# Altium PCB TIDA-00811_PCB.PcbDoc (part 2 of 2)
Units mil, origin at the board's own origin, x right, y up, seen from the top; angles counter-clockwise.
Board outline 3346.46 x 1968.5 mil, 2 copper layers (Top Layer, Bottom Layer), stack 62 mil thick; 221 components, 100 nets, 529 pads, 192 vias.
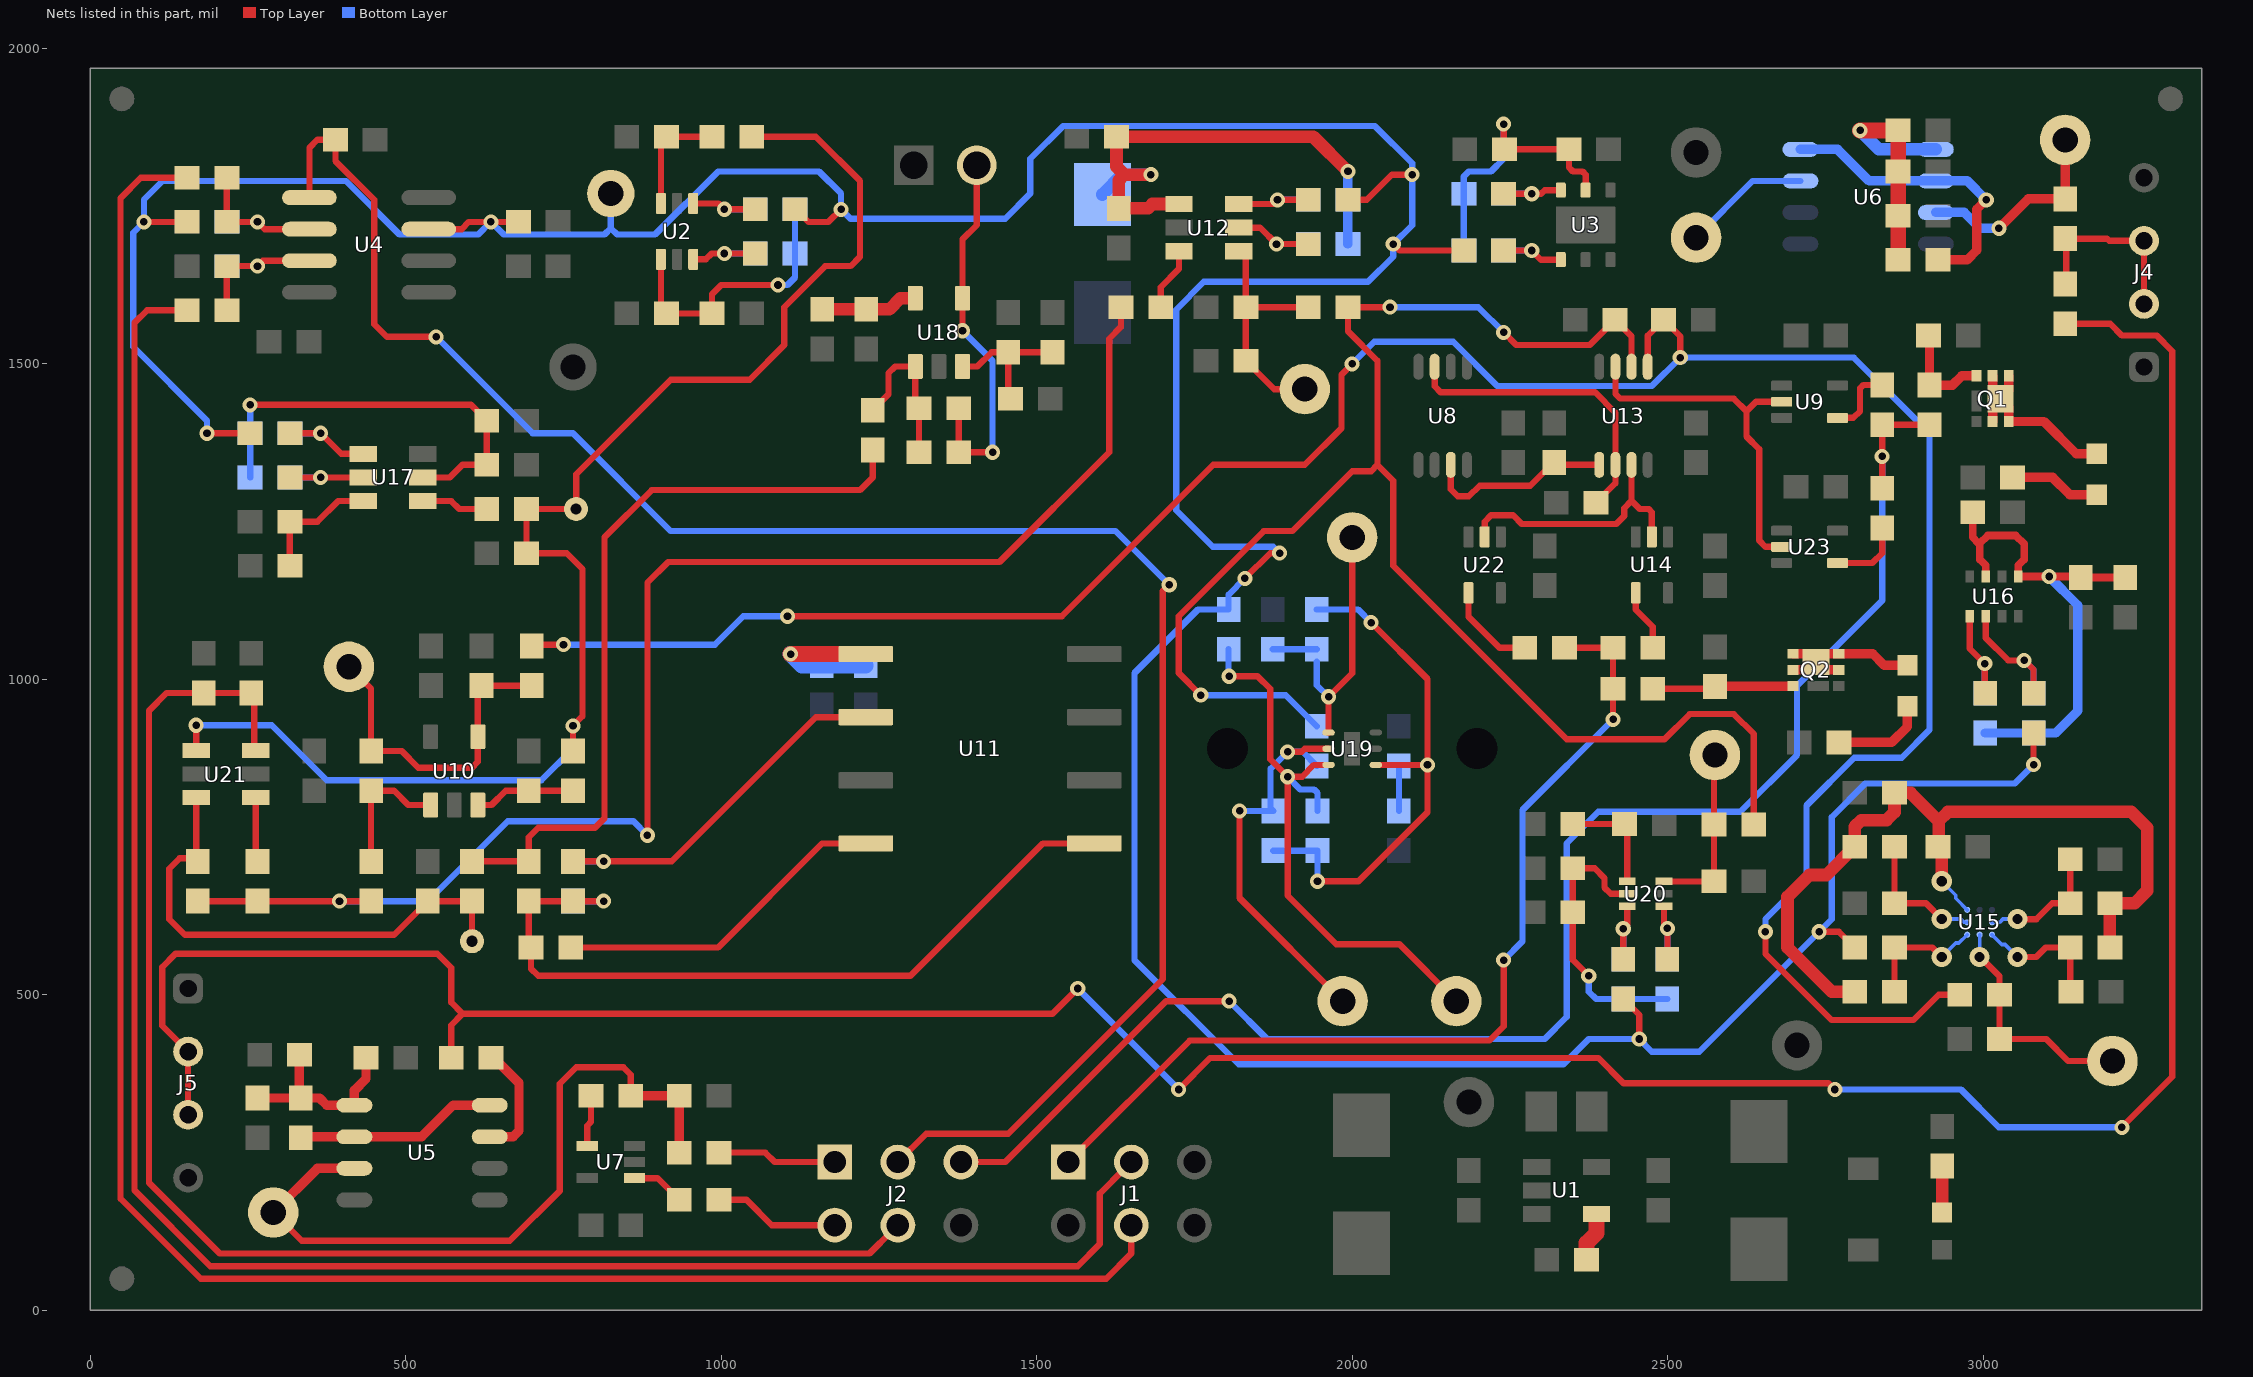
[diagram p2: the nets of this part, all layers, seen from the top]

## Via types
v1: diameter 24, hole 12, Top Layer to Bottom Layer, tented both sides, 177 vias
v2: diameter 32, hole 16, Top Layer to Bottom Layer, tented both sides, 8 vias
v3: diameter 19.68, hole 7.87, Top Layer to Bottom Layer, 7 vias

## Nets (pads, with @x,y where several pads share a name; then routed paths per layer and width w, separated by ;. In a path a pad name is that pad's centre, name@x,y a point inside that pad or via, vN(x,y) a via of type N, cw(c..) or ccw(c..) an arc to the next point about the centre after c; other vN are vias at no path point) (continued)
I2C_SDA: R4.1 R18.2 R23.2 R33.2 R47.1 R56.1 R58.1 R63.2 R72.2 R97.2 TP17.1 U4.3 | length 7194.7
  Top Layer w10: v1(85,1725) R72.2@153.5,1725 ; v1(185,1390) R47.1@253.35,1390 ; U4.3@536.34,1713.5 588.5,1713.5 600,1725 v1(635,1725) R4.1@678.5,1725 ; R23.2@1116.85,1744.93 1118.28,1744.93 1138.21,1725 1170,1725 v1(1189.93,1744.93) v1@1190,1745 ; v1(1830,1160) 1870,1200 v1(1885,1200) ; R33.2@1993.35,1759.93 2022.93,1759.93 2063,1800 v1(2095,1800) ; v1(2065.07,1689.93) 2075.31,1679.68 R18.2@2177.01,1679.68 ; R97.2@2429.65,493.5 2455,468.15 v1(2455,430) ; v1(2740,600) 2771.48,600 R58.1@2796.51,574.97 ; v1(3080,865) R56.1@3080,915
  Bottom Layer w10: v1(185,1390) 185,1410 68,1527 68,1708 v1(85,1725) 85,1760 115,1790 405,1790 490,1705 615,1705 v1(635,1725) 655,1705 815,1705 825,1715 ; TP17.1@825,1770 825,1715 ; v1(1830,1160) 1804.09,1134.09 R63.2@1804.09,1110.67 1755.67,1110.67 1655,1010 1655,555 1820,390 2335,390 2375,430 v1(2455,430) 2475,410 2550,410 v1(2740,600) 2760,620 2760,781.72 2813.28,835 3050,835 v1(3080,865) ; v1(1885,1200) 1875,1210 1779,1210 1721,1268 1721,1586 1765,1630 2025,1630 2065.07,1670.07 v1(2065.07,1689.93) 2095,1719.87 v1(2095,1800) 2095,1818 2036,1877 1542,1877 1490,1825 1490,1770 1450,1730 1204.87,1730 v1(1189.93,1744.93) 1189.93,1770.07 1155,1805 995,1805 895,1705 835,1705 825,1715
INTERRUPT: R35.2 R64.2 R79.1 R92.2 U13.2 | length 2606.7
  Top Layer w10: v1(1760,975) 1725,1010 1725,1100 1860,1235 1905,1235 2000,1330 2030,1330 2040,1340 ; v1(2060,1590) R35.2@1993.35,1590 1993.35,1551.65 2040,1505 2040,1340 ; v1(2240,1550) 2260,1530 2376.43,1530 R79.1@2416.5,1570.07 2442.8,1543.77 U13.2@2442.8,1495.51 ; R92.2@2636.5,770 2636.5,913.5 2605,945 2535,945 2495,905 2340,905 2065,1180 2065,1315 2040,1340
  Bottom Layer w10: v1(1760,975) 1894.76,975 R64.2@1944.09,925.67 ; v1(2060,1590) 2200,1590 v1(2240,1550)
IR_ALERT: R59.2 R78.1 R89.2 U13.1 | length 4059.4
  Top Layer w10: R59.2@700,1052.99 702.01,1055 v1(750,1055) ; v1(1105,1100) 1540,1100 1780,1340 1925,1340 1983,1398 1983,1483 v1(2000,1500) ; U13.1@2468.39,1495.51 2468.39,1544.88 R78.1@2493.5,1570 2520,1543.5 v1(2520,1510) ; v1(2655,600) 2655,565 2760,460 2889.48,460 2929.45,499.97 R89.2@2963.01,499.97
  Bottom Layer w10: v1(750,1055) 990,1055 1035,1100 v1(1105,1100) ; v1(2000,1500) 2035,1535 2160,1535 2230,1465 2475,1465 v1(2520,1510) ; v1@2525,1505 2530,1510 2795,1510 2915,1390 2915,920 2871,876 2796,876 2720,800 2720,685 2655,620 v1(2655,600)
LIGHT_DIAG: C26.2 R39.2 R45.2 R104.2 TP4.1 U21.1 | length 2276.4
  Top Layer w10: U21.1@167.76,887.4 v1(167.76,927.24) ; R104.2@765.07,886.5 v1(765.07,926.34) 780,941.27 780,1175 755,1200 C26.2@691.34,1200 R45.2@691.34,1270 TP4.1@770,1270 770,1325 920,1475 1045,1475 1100,1530 1100,1590 1165,1655 1205,1655 1220,1670 1220,1790 1150,1860 R39.2@1048.35,1860
  Bottom Layer w10: v1(167.76,927.24) 287.76,927.24 375,840 715,840 765.07,890.07 v1(765.07,926.34)
LIGHT_LEVEL: R104.1 R105.1 U10.3 | length 160.2
  Top Layer w10: U10.3@614.25,800.87 635.87,800.87 658.5,823.5 R105.1@695,823.5 R104.1@765.07,823.5
LIGHT_OUT: C18.2 R25.2 R103.1 TP3.1 U21.3 | length 804.9
  Top Layer w10: U21.3@167.76,812.6 167.76,718.74 170,716.5 141.5,716.5 125,700 125,620 150,595 481.5,595 C18.2@535,648.5 R25.2@605,648.5 TP3.1@605,585
LIGHT_SENSE: R26.1 R66.2 R102.1 R103.2 | length 2279.9
  Top Layer w10: R103.2@170,648.5 R102.1@265,648.5 v1(395,648.5) R26.1@445,648.5 ; v1(883,753) 883,1153 916,1186 1441,1186 1615,1360 1615,1540 1633.5,1558.5 R66.2@1633.5,1590
  Bottom Layer w10: v1(395,648.5) 535,648.5 661.5,775 861,775 v1(883,753)
MCU_EN: J2.3 R3.1 U4.5 | length 3043
  Top Layer w10: U4.5@347.36,1763.5 347.36,1842.36 360,1855 R3.1@388.5,1855 388.5,1821.5 450,1760 450,1563 470.14,1542.86 v1(548.14,1542.86) ; J2.3@1280,235 1325,280 1455,280 1700,525 1700,1140 v1(1710,1150)
  Bottom Layer w10: v1(548.14,1542.86) 701,1390 765,1390 920,1235 1625,1235 v1(1710,1150)
MCU_INT: J2.5 R85.1 R109.2 R110.2 | length 2507.7
  Top Layer w10: J2.5@1380,235 1450,235 1705,490 v1(1805,490) ; R110.2@2840.07,1302.99 2840,1303.06 v1(2840,1353.28) R109.2@2840,1403.5 R85.1@2915,1403.5
  Bottom Layer w10: v1(1805,490) 1865,430 2305,430 2340,465 2340,740 2390,790 2615,790 2705,880 2705,990 2840,1125 v1(2840,1353.28)
MCU_INT1: J1.1 R86.1 R107.2 R108.2 | length 1527.9
  Top Layer w10: J1.1@1550,235 1742.5,427.5 2217.5,427.5 2240,450 v1(2240,555) ; R108.2@2336.5,1050 R107.2@2413.5,1050 R86.1@2413.5,985 v1(2413.5,936.5)
  Bottom Layer w10: v1(2240,555) 2270,585 2270,792.99 v1(2413.5,936.5)
MCU_SCL: J1.3 R8.2 | length 3207.6
  Top Layer w10: R8.2@153.5,1585 90,1585 70,1565 70,190 190,70 1565,70 1600,105 1600,185 1640,225 J1.3@1650,225
MCU_SDA: J1.4 R9.2 | length 3410.9
  Top Layer w10: R9.2@153.5,1795 80,1795 48,1763 48,177 175,50 1610,50 1650,90 J1.4@1650,125
NetC5_2: C5.2 R20.2 R21.2 R71.1 U2.1 | length 442.4
  Top Layer w10: U2.1@904.41,1665.71 904.41,1588.94 C5.2@913.35,1580 R71.1@985.35,1580 985.35,1610.35 1000,1625 v1(1090,1625)
  Bottom Layer w10: v1(1090,1625) 1105,1625 1116.85,1636.85 R21.2@1116.85,1675 R20.2@1116.85,1745
NetC6_1: C6.1 U1.4 | length 79.1
  Top Layer w25: C6.1@2371.5,80 2371.5,106.5 2387.24,122.24 U1.4@2387.24,152.6
NetC7_2: C7.2 R15.2 R16.2 R77.1 U3.5 | length 474.3
  Top Layer w10: v1(2240,1880) 2240,1841.5 R77.1@2241.5,1840 2343.19,1840 C7.2@2343.5,1840.32 2343.5,1811.5 2350,1805 2365,1805 2370,1800 U3.5@2370,1775.43
  Bottom Layer w10: R16.2@2177.01,1679.68 R15.2@2177.01,1769.68 2177.01,1797.01 2185,1805 2220,1805 2240,1825 v1(2240,1880)
NetC9_1: C9.1 C11.2 R10.1 R87.2 U5.1 | length 310.3
  Top Layer w15: C9.1@265,336.5 R10.1@333.5,336.5 ; R87.2@331.5,405 331.5,338.5 R10.1@333.5,336.5 ; C11.2@437.01,400 437.01,367.01 418.5,348.5 U5.1@418.5,325 374.77,325 363.27,336.5 R10.1@333.5,336.5
NetC10_1: C10.1 C12.2 R11.1 R88.2 U6.1 | length 397.8
  Top Layer w25: v1(2805,1870) R88.2@2865.35,1870 C12.2@2865.35,1805 C10.1@2865.35,1735 R11.1@2865.35,1665
  Bottom Layer w20: v1(2805,1870) 2835,1840 U6.1@2925,1840
NetC17_2: C17.2 R74.1 U11.1 | length 245.6
  Top Layer w25: v1(1110,1040) U11.1@1229.09,1040
  Bottom Layer w25: v1(1110,1040) 1127.83,1022.17 R74.1@1159.09,1022.17 C17.2@1229.09,1022.17
NetC19_2: C19.2 C37.1 R30.2 R31.2 R75.1 U12.1 | length 860.8
  Top Layer w20: v1(1681,1800) 1639,1800 ; U12.1@1725.51,1753.39 1683.39,1753.39 1676.5,1746.5 C19.2@1630,1746.5 1630,1791 1639,1800 ; v1(1993.35,1805) 1938.35,1860 R75.1@1626.5,1860 1626.5,1812.5 1639,1800
  Bottom Layer w15: R30.2@1993.35,1690 R31.2@1993.35,1760 v1(1993.35,1805) v1@1993.35,1808.35
  Bottom Layer w20: C37.1@1604,1768.5 1635.5,1800 v1(1681,1800)
NetC22_2: C22.2 C24.2 R2.2 R51.2 R52.2 U16.6 U16.8 | length 811.1
  Top Layer w12: C22.2@2983.5,1265 2983.5,1225 2992.63,1215.87 2995,1215.87 ; U16.6@3004.41,1162.99 3004.41,1180.59 2995,1190 2995,1215.87 ; R2.2@3225,1161.5 C24.2@3155,1161.5 3153.5,1162.99 v1(3104.55,1162.99) U16.8@3055.59,1162.99 3055.59,1180.59 3065,1190 3065,1215 3052,1228 3007.13,1228 2995,1215.87
  Bottom Layer w15: R51.2@3003.63,915 R52.2@3080,915 3115,915 3150,950 3150,1117.54 v1(3104.55,1162.99)
NetC23_2: C23.2 R53.2 R54.2 R68.2 R69.2 R70.1 U15.A3 | length 1322
  Top Layer w20: R54.2@2796.51,504.97 2760.03,504.97 2690,575 2690,655.25 2724.75,690 2751.51,690 R53.2@2796.51,735 2796.51,766.51 2807,777 2847,777 2859.51,789.51 R70.1@2859.51,820 2885,820 2929.51,775.49 ; v2(2934.51,679.97) 2934.51,735.97 2929.51,740.97 2929.51,775.49 ; R69.2@3201,574.97 R68.2@3201,644.97 3239.97,644.97 3260,665 3260,765 3235,790 2944.01,790 2929.51,775.49
  Bottom Layer w6: v2(2934.51,679.97) 2956.51,657.97 2956.51,652.97 U15.A3@2974.82,634.65
NetC25_1: C25.1 R41.2 R48.1 U18.1 | length 254.3
  Top Layer w10: R48.1@1240,1426.5 1265,1451.5 1265,1485 1275.87,1495.87 U18.1@1307.6,1495.87 1307.6,1435.91 C25.1@1313.5,1430 R41.2@1313.5,1360
NetC25_2: C25.2 D5.2 R41.1 U18.4 | length 607.6
  Top Layer w10: C25.2@1376.5,1430 R41.1@1376.5,1360 v1(1430,1360) ; v1(1382.4,1552.6) U18.4@1382.4,1604.13 1382.4,1697.4 1405,1720 D5.2@1405,1815
  Bottom Layer w10: v1(1382.4,1552.6) 1430,1505 v1(1430,1360)
NetC27_1: C27.1 R42.2 R43.2 R67.1 U17.2 | length 679.9
  Top Layer w10: v1(253.35,1435) 603.35,1435 R67.1@628.35,1410 C27.1@628.35,1340 590,1340 570,1320 U17.2@527.09,1320
  Bottom Layer w10: R42.2@253.35,1320 R43.2@253.35,1390 v1(253.35,1435)
NetC28_2: C28.2 R60.2 R61.2 R76.1 R115.2 U19.1 | length 969.5
  Top Layer w10: v1(1945,680) 2010,680 2119.41,789.41 v1(2119.41,864.41) ; v1(2030,1090) 2119.41,1000.59 v1(2119.41,864.41) ; U19.1@2037.4,864.41 v1(2119.41,864.41)
  Bottom Layer w10: R115.2@1875,728.5 R61.2@1945,728.5 v1(1945,680) ; R60.2@1944.09,1110.67 2009.33,1110.67 v1(2030,1090) ; R76.1@2074.09,791.5 C28.2@2074.09,862.68 2075.83,864.41 v1(2119.41,864.41)
NetC29_1: C29.1 Q1.3 R85.2 | length 159.7
  Top Layer w15: C29.1@2913.5,1545 2915,1543.5 R85.2@2915,1466.5 2951.5,1466.5 2966.32,1481.32 Q1.3@2989.41,1481.32
NetC30_1: C30.1 Q2.3 R86.2 | length 224
  Top Layer w10: R86.2@2476.5,985 2571.5,985 C30.1@2575,988.5
  Top Layer w15: C30.1@2575,988.5 2575.91,989.41 Q2.3@2698.68,989.41
NetC31_2: C31.2 R90.1 R94.2 R95.2 U20.5 | length 447.4
  Top Layer w10: v1(2375,530) 2349.65,555.35 R90.1@2349.65,630.68 C31.2@2349.65,700.62 2384.38,700.62 2400,685 2400,670 2410,660 U20.5@2435.87,660
  Bottom Layer w10: v1(2375,530) 2375,505 2386.5,493.5 R94.2@2429.65,493.5 R95.2@2499.65,493.5
NetC35_2: C35.2 R44.1 U18.5 | length 154.9
  Top Layer w20: R44.1@1160,1586.5 C35.2@1230,1586.5 1266.5,1586.5 1284.13,1604.13 U18.5@1307.6,1604.13
NetC36_1: C36.1 R27.2 R28.1 R40.1 U11.5 | length 1260
  Top Layer w10: v1(813.5,648.5) R27.2@765,648.5 R40.1@695,648.5 695,578.5 R28.1@698.5,575 698.5,541.5 710,530 1300,530 1510,740 U11.5@1591.3,740
  Bottom Layer w10: C36.1@765,648.5 v1(813.5,648.5)
NetC36_2: C36.2 R27.1 U11.2 | length 607.2
  Top Layer w10: R27.1@765,711.5 v1(813.5,711.5) 921.5,711.5 1150,940 U11.2@1229.09,940
  Bottom Layer w10: C36.2@765,711.5 v1(813.5,711.5)
NetC38_1: C38.1 R106.2 R111.2 U18.3 | length 226.9
  Top Layer w10: U18.3@1382.4,1495.87 1405.87,1495.87 1428.5,1518.5 C38.1@1455,1518.5 ; R106.2@1458.5,1445 1455,1448.5 C38.1@1455,1518.5 ; R111.2@1525,1518.5 C38.1@1455,1518.5
NetD2_1: D2.1 R1.1 | length 73.5
  Top Layer w20: D2.1@2935,155 R1.1@2935,228.5
NetD3_1: D3.1 Q1.1 Q1.2 Q1.5 Q1.6 Q1.8 | length 327.1
  Top Layer w15: Q1.5@3015,1408.68 3015,1432.2 Q1.8@3027.8,1445 ; Q1.2@3015,1481.32 3015,1457.8 Q1.8@3027.8,1445 ; Q1.1@3040.59,1481.32 3040.59,1457.8 Q1.8@3027.8,1445 ; D3.1@3180,1357.48 3147.52,1357.48 3096.32,1408.68 Q1.6@3040.59,1408.68 3040.59,1432.2 Q1.8@3027.8,1445
NetD3_2: D3.2 R83.1 | length 144.9
  Top Layer w15: R83.1@3046.5,1320 3110,1320 3137.48,1292.52 D3.2@3180,1292.52
NetD4_1: D4.1 Q2.1 Q2.2 Q2.5 Q2.6 Q2.8 | length 282.7
  Top Layer w15: Q2.2@2698.68,1015 2722.2,1015 Q2.8@2735,1027.8 ; Q2.1@2698.68,1040.59 2722.2,1040.59 Q2.8@2735,1027.8 ; Q2.5@2771.32,1015 2747.8,1015 Q2.8@2735,1027.8 ; D4.1@2880,1022.48 2843.11,1022.48 2825,1040.59 Q2.6@2771.32,1040.59 2747.8,1040.59 Q2.8@2735,1027.8
NetD4_2: D4.2 R84.1 | length 151.4
  Top Layer w15: R84.1@2771.5,900 2855,900 2880,925 D4.2@2880,957.52
NetJ4_2: J4.2 J4.3 R80.1 R82.2 | length 293.5
  Top Layer w10: R80.1@3130,1698.5 3196.5,1698.5 3200,1695 J4.3@3255,1695 J4.2@3255,1595 ; R82.2@3131.85,1616.5 R80.1@3131.85,1683.5
NetJ5_2: J5.2 J5.3 R81.2 R82.1 | length 5115
  Top Layer w10: J5.3@155,310 J5.2@155,410 114,451 114,544 135,565 550,565 572.01,542.99 572.01,487.99 590,470 ; R81.2@572.01,400 572.01,452.01 590,470 ; v1(1565,510) 1525,470 590,470 ; v1(1725,350) 1775,400 2390,400 2430,360 2755,360 v1(2765,350) ; R82.1@3130,1563.5 3201.5,1563.5 3220,1545 3275,1545 3300,1520 3300,370 v1(3220,290)
  Bottom Layer w10: v1(1565,510) v1(1725,350) ; v1(2765,350) 2965,350 3025,290 v1(3220,290)
NetR6_1: R6.1 R8.1 R73.1 U4.7 | length 252.9
  Top Layer w10: R8.1@216.5,1585 R73.1@216.5,1655 v1(265,1655) 273.5,1663.5 U4.7@347.36,1663.5
  Bottom Layer w10: R6.1@216.5,1655 v1(265,1655)
NetR7_1: R7.1 R9.1 R72.1 U4.6 | length 254.1
  Top Layer w10: R9.1@216.5,1795 R72.1@216.5,1725 v1(265,1725) 276.5,1713.5 U4.6@347.36,1713.5
  Bottom Layer w10: R7.1@216.5,1725 v1(265,1725)
NetR10_2: R10.2 U5.2 U5.8 | length 320.9
  Top Layer w15: R10.2@333.5,273.5 335,275 U5.2@418.5,275 525,275 575,325 U5.8@633.07,325
NetR11_2: R11.2 U6.2 U6.8 | length 481.8
  Top Layer w15: R11.2@2928.35,1665 2975,1665 2990,1680 2990,1745 v1(3005,1760)
  Bottom Layer w15: U6.8@2710.43,1840 2769.37,1840 2819.37,1790 U6.2@2925,1790 2975,1790 v1(3005,1760)
NetR12_1: R12.1 R13.2 R14.2 TP11.1 U5.3 | length 1154.3
  Top Layer w10: TP11.1@295,150 335,110 665,110 744,189 744,359 770,385 845,385 856.5,373.5 R13.2@856.5,340
  Top Layer w15: TP11.1@290,155 360,225 U5.3@418.5,225 ; R13.2@856.5,340 R12.1@933.5,340 R14.2@933.5,250
NetR13_1: R13.1 U7.4 | length 81.9
  Top Layer w10: U7.4@787.6,260.59 787.6,292.6 793.5,298.5 R13.1@793.5,340
NetR15_1: R15.1 R17.1 U3.6 | length 137.7
  Top Layer w10: R17.1@2240,1769.68 v1(2284.69,1769.68) 2299.29,1769.68 2305.04,1775.43 U3.6@2330.63,1775.43
  Bottom Layer w10: R15.1@2240,1769.68 v1(2284.69,1769.68)
NetR16_1: R16.1 R18.1 U3.1 | length 141.3
  Top Layer w10: R18.1@2240,1679.68 v1(2284.69,1679.68) 2299.17,1665.2 U3.1@2330.63,1665.2
  Bottom Layer w10: R16.1@2240,1679.68 v1(2284.69,1679.68)
NetR19_2: R19.2 R39.1 U2.6 | length 181.4
  Top Layer w10: U2.6@904.41,1754.29 904.41,1851.06 R19.2@913.35,1860 R39.1@985.35,1860
NetR20_1: R20.1 R23.1 U2.4 | length 151
  Top Layer w10: U2.4@955.59,1754.29 995.71,1754.29 v1(1005,1745) 1005.07,1744.93 R23.1@1053.86,1744.93
  Bottom Layer w10: v1(1005,1745) R20.1@1053.86,1745
NetR21_1: R21.1 R22.1 U2.3 | length 150.9
  Top Layer w10: U2.3@955.59,1665.71 975.71,1665.71 984.93,1674.93 R22.1@1053.86,1674.93
  Bottom Layer w10: v1(1005,1675) R21.1@1053.86,1675
NetR24_1: R24.1 R29.2 R59.1 TP13.1 U10.4 | length 535.2
  Top Layer w10: TP13.1@410,1020 445,985 R29.2@445,886.5 493.5,886.5 520,860 605,860 614.25,869.25 U10.4@614.25,909.13 614.25,984.25 R24.1@620,990 R59.1@700,990
NetR25_1: R25.1 R40.2 R48.2 | length 1213.8
  Top Layer w10: R25.1@605,711.5 R40.2@695,711.5 695,750 710,765 800,765 815,780 815,1225 890,1300 1220,1300 1240,1320 R48.2@1240,1363.5
NetR26_2: R26.2 R29.1 U10.1 | length 215.8
  Top Layer w10: R26.2@445,711.5 R29.1@445,823.5 481.5,823.5 504.13,800.87 U10.1@539.45,800.87
NetR28_2: R28.2 U11.4 | length 543
  Top Layer w10: R28.2@761.5,575 R28.2@766.5,575 ; R28.2@761.5,580 R28.2@766.5,575 ; U11.4@1229.09,740 1160,740 995,575 R28.2@766.5,575
NetR30_1: R30.1 R34.1 U12.5 | length 171.5
  Top Layer w10: U12.5@1820,1715.98 1854.02,1715.98 v1(1880.07,1689.93) R34.1@1930.35,1689.93
  Bottom Layer w10: v1(1880.07,1689.93) 1880.13,1690 R30.1@1930.35,1690
NetR31_1: R31.1 R33.1 U12.6 | length 161.9
  Top Layer w10: U12.6@1820,1753.39 1875,1753.39 1881.55,1759.93 R33.1@1930.35,1759.93
  Bottom Layer w10: v1@1881.55,1759.93 v1(1881.61,1760) R31.1@1930.35,1760
NetR32_1: R32.1 R35.1 R114.1 TP14.1 U12.4 | length 410.2
  Top Layer w10: U12.4@1820,1678.58 1831.5,1678.58 R32.1@1831.5,1590 ; TP14.1@1925,1460 1876.5,1460 R114.1@1831.5,1505 1841.5,1505 1831.5,1515 R32.1@1831.5,1590 ; R35.1@1930.35,1590 R32.1@1831.5,1590
NetR36_1: R36.1 R89.1 TP12.1 U15.C2 | length 372.5
  Top Layer w10: v2(2994.51,559.97) 2995.71,559.97 3026,529.67 R89.1@3026,499.97 R36.1@3026,429.97 3100.03,429.97 3135,395 TP12.1@3205,395
  Bottom Layer w6: v2(2994.51,559.97) U15.C2@2994.51,595.28
NetR37_2: R37.2 R69.1 U15.C1 | length 215.3
  Top Layer w10: v2(3054.51,559.97) 3084.51,559.97 3099.51,574.97 R69.1@3138.01,574.97 3138.01,506.46 R37.2@3139.51,504.97
  Bottom Layer w6: U15.C1@3014.19,595.28 3029.51,579.97 3034.51,579.97 v2(3054.51,559.97)
NetR38_2: R38.2 R68.1 U15.B1 | length 208.5
  Top Layer w10: v2@3054.51,622.22 v2(3054.51,619.97) 3084.52,619.97 3109.52,644.97 R68.1@3138.01,644.97 R38.2@3138.01,714.97
  Bottom Layer w6: U15.B1@3014.19,614.97 3026.51,614.97 3031.51,619.97 v2(3054.51,619.97)
NetR42_1: R42.1 R46.2 U17.5 | length 164.9
  Top Layer w10: R46.2@316.34,1320 v1(365,1320) U17.5@432.6,1320
  Bottom Layer w10: R42.1@316.34,1320 v1(365,1320)
NetR43_1: R43.1 R47.2 U17.4 | length 178.4
  Top Layer w10: R47.2@316.34,1390 v1(365,1390) 397.6,1357.4 U17.4@432.6,1357.4
  Bottom Layer w10: R43.1@316.34,1390 v1(365,1390)
NetR45_1: R45.1 U17.1 | length 106.5
  Top Layer w10: U17.1@527.09,1282.6 572.4,1282.6 585,1270 R45.1@628.35,1270
NetR49_2: R49.2 R50.2 U17.6 | length 199.8
  Top Layer w10: R50.2@316.5,1180 316.34,1180.16 R49.2@316.34,1250 360,1250 392.6,1282.6 U17.6@432.6,1282.6
NetR51_1: R51.1 R55.2 U16.4 | length 181.1
  Top Layer w10: U16.4@2978.82,1100 2978.82,1048.82 v1(3002.64,1025) 3002.64,978.99 R55.2@3003.63,977.99
  Bottom Layer w10: R51.1@3003.63,977.99 3002.64,978.99 v1(3002.64,1025) v1@3003.63,1024
NetR52_1: R52.1 R56.2 U16.3 | length 226.2
  Top Layer w10: U16.3@3004.41,1100 3004.41,1065.59 3040,1030 v1(3065,1030) 3080,1015 R56.2@3080,977.99
  Bottom Layer w10: v1(3065,1030) 3080,1015 R52.1@3080,977.99
NetR53_1: R53.1 R57.2 U15.B3 | length 217.8
  Top Layer w10: R53.1@2859.51,735 R57.2@2859.51,644.97 2909.51,644.97 v2(2934.51,619.97)
  Bottom Layer w6: v2(2934.51,619.97) 2964.51,619.97 2969.51,614.97 U15.B3@2974.82,614.97
NetR54_1: R54.1 R58.2 U15.C3 | length 200.2
  Top Layer w10: R54.1@2859.51,504.97 R58.2@2859.51,568.97 ; R58.2@2859.51,574.97 2919.51,574.97 v2(2934.51,559.97)
  Bottom Layer w6: v2(2934.51,559.97) 2956.51,581.97 2961.51,581.97 U15.C3@2974.82,595.28
NetR60_1: R60.1 R62.1 TP7.1 U19.4 | length 457.8
  Top Layer w10: U19.4@1962.6,915.59 v1(1962.6,972.4) 2000,1009.8 TP7.1@2000,1225
  Bottom Layer w10: R62.1@1874.09,1047.68 R60.1@1944.09,1047.68 ; 1944.09,1027.68 1944.09,990.91 v1(1962.6,972.4)
NetR61_1: R61.1 R63.1 TP5.1 U19.6 | length 951.2
  Top Layer w10: v1(1805,1005) 1850,1005 1870,985 1870,873.4 v1(1897.68,845.72) ; U19.6@1962.6,864.41 1939.41,864.41 1920.72,845.72 v1(1897.68,845.72) ; TP5.1@2165,490 2075,580 1975,580 1897.68,657.32 v1(1897.68,845.72)
  Bottom Layer w10: R63.1@1804.09,1047.68 1804.09,1005.91 v1(1805,1005) ; v1(1897.68,845.72) 1917.93,825.47 1939.51,825.47 1945,819.98 R61.1@1945,791.5
NetR64_1: R64.1 R115.1 TP9.1 U19.5 | length 652
  Top Layer w10: v1(1821.5,791.5) 1821.5,653.5 TP9.1@1985,490 ; v1(1897.68,885.11) 1920.11,885.11 1925,890 U19.5@1962.6,890
  Bottom Layer w10: v1(1821.5,791.5) R115.1@1875,791.5 1870.68,795.82 1870.68,858.11 v1(1897.68,885.11) 1921.66,885.11 R64.1@1944.09,862.68
NetR65_1: R65.1 U7.1 | length 85.4
  Top Layer w10: U7.1@862.4,209.41 899.09,209.41 R65.1@933.5,175
NetR66_1: R66.1 U12.3 | length 100.6
  Top Layer w10: R66.1@1696.5,1590 1696.5,1621.5 1725.51,1650.51 U12.3@1725.51,1678.58
NetR80_2: R80.2 TP10.1 U6.3 | length 353.1
  Top Layer w15: v1(3025,1715) 3071.5,1761.5 R80.2@3130,1761.5 TP10.1@3130,1855 TP10.1@3130,1880
  Bottom Layer w15: U6.3@2925,1740 2970,1740 2995,1715 v1(3025,1715)
NetR81_1: R81.1 U5.7 | length 187.2
  Top Layer w15: U5.7@633.07,275 670,275 679.5,284.5 679.5,360.5 640,400 R81.1@635,400
NetR91_1: R91.1 R92.1 TP15.1 U20.3 | length 280.1
  Top Layer w10: U20.3@2494.13,679.68 2573.19,679.68 R91.1@2573.5,680 R92.1@2573.5,770 2573.5,878.5 TP15.1@2575,880
NetR93_1: R93.1 R98.1 U20.4 | length 174.8
  Top Layer w10: R98.1@2349.65,770.75 2349.71,770.68 R93.1@2431.65,770.68 2435.87,766.47 U20.4@2435.87,679.68
NetR94_1: R94.1 R97.1 U20.6 | length 134.5
  Top Layer w10: R97.1@2429.65,556.5 v1(2429.65,604.65) 2435.87,610.87 U20.6@2435.87,640.31
  Bottom Layer w10: R94.1@2429.65,556.5 v1(2429.65,604.65)
NetR95_1: R95.1 R96.1 U20.1 | length 135
  Top Layer w10: U20.1@2494.13,640.31 2494.13,610.87 v1(2499.65,605.35) R96.1@2499.65,556.5
  Bottom Layer w10: R95.1@2499.65,556.5 v1(2499.65,605.35)
NetR102_2: R102.2 U21.4 | length 97.2
  Top Layer w10: U21.4@262.24,812.6 262.24,719.25 R102.2@265,716.5
NetR107_1: R107.1 U14.4 | length 98.4
  Top Layer w10: U14.4@2449.41,1137.2 2449.41,1110.59 2476.5,1083.5 R107.1@2476.5,1050
NetR108_1: R108.1 U22.4 | length 147.5
  Top Layer w10: U22.4@2184.41,1137.2 2184.41,1099.09 2233.5,1050 R108.1@2273.5,1050
NetR109_1: R109.1 U9.4 | length 113.5
  Top Layer w10: U9.4@2769.29,1414.41 2794.41,1414.41 2805,1425 2805,1461.2 2810.3,1466.5 R109.1@2840,1466.5
NetR110_1: R110.1 U23.4 | length 117.2
  Top Layer w10: U23.4@2769.29,1184.41 2824.41,1184.41 2840.07,1200.07 R110.1@2840.07,1240
NetR112_1: R112.1 U8.7 U13.5 | length 302.4
  Top Layer w10: U8.7@2156.26,1340 2156.26,1301.26 2167.52,1290 2185,1290 2202,1307 2282,1307 2318.5,1343.5 R112.1@2320,1343.5 2323.5,1340 U13.5@2391.61,1340
NetR113_2: R113.2 U8.3 U13.6 | length 490.4
  Top Layer w10: U8.3@2130.67,1495.51 2130.67,1464.33 2140,1455 2385,1455 2417.2,1422.8 U13.6@2417.2,1340 2417.2,1310.71 R113.2@2386.5,1280
NetTP8_1: TP8.1 U6.7 | length 202.7
  Bottom Layer w10: TP8.1@2545,1700 2635,1790 U6.7@2710.43,1790
NetU9_2: U9.2 U13.3 U23.2 | length 577.1
  Top Layer w10: U13.3@2417.2,1495.51 2417.2,1452.8 2425,1445 2605,1445 2625,1425 ; U23.2@2680.71,1210 2655,1210 2645,1220 2645,1365 2625,1385 2625,1425 ; U9.2@2680.71,1440 2640,1440 2625,1425
NetU13_7: U13.7 U14.2 U22.2 | length 425.2
  Top Layer w10: U22.2@2210,1225.79 2210,1250 2220,1260 2255,1260 2268.7,1246.3 2418.7,1246.3 2431.4,1259 2431.4,1271.4 2442.8,1282.8 ; U13.7@2442.8,1340 2442.8,1282.8 ; U14.2@2475,1225.79 2475,1265 2470,1270 2455.59,1270 2442.8,1282.8
RXD: J2.1 R14.1 | length 193.9
  Top Layer w10: R14.1@996.5,250 1070,250 1085,235 1170,235 J2.1@1180,225
TEST_SEL: J2.4 R100.2 R101.2 U21.6 | length 2263.9
  Top Layer w10: U21.6@262.24,887.4 260,889.65 260,973.5 R100.2@255,978.5 R101.2@180,978.5 121.38,978.5 93,950.13 93,202 205,90 1235,90 1270,125 J2.4@1280,125
TXD: J2.2 R65.2 | length 204.2
  Top Layer w10: R65.2@996.5,175 1040,175 1080,135 1170,135 J2.2@1180,125
pads on no net: FID1.1 FID2.1 FID3.1 FID4.1 FID5.1 FID6.1 H2.0 H3.0 H4.0 H5.0 U3.3 U3.4 U4.1 U9.1 U11.6 U11.7 U14.1 U22.1 U23.1

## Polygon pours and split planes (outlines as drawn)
GND on Bottom Layer "GND_L02_P000" (solid, remove dead copper, pour order 0): 35,1857.06 110,1932.06 120,1932.06 3240,1932.06 3315,1857.06 3315,1802.06 3315,57.06 3290,32.06 3245,32.06 115,32.06 30,117.06 30,1852.06

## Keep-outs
Keep-Out Layer:
  lines w8: 25,26 25,1943.5 3321.46,1943.5 3321.46,26 25,26

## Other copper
Top Layer:
  text ".Layer_Name" at 523.85,-858.49 h60
Bottom Layer:
  pour cut-out: 1549,1520 1660,1520 1660,1640 1549,1640
  pour cut-out: 2645,1930 2645,1590 2990,1590 2990,1930
  pour cut-out: 3139.51,474.97 2849.51,474.97 2849.51,764.97 2974.51,764.97 2974.51,724.97 2889.51,724.97 2889.51,514.97 3099.51,514.97 3099.51,724.97 3024.51,724.97 3024.51,764.97 3139.51,764.97
  pour cut-out: 1196.21,925.67 1266.21,925.67 1266.21,985.67 1196.21,985.67
  region net GND: 2986.51,622.97 2986.51,607.97 3001.51,607.97 3001.51,622.97
  text ".Layer_Name" at 523.85,-858.49 h60
Multi-Layer:
  pour cut-out: 3037.99,573.51 3037.99,663.51 2947.99,663.51 2947.99,573.51

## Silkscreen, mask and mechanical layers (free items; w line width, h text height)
Top Overlay:
  circle w6: c2526,640 r5.83
  circle w10: c2245,225 r8.53
  circle w6: c885,185 r5
  lines w6: 210,145 220,155 220,227.22 237.8,245.02 ; 340,245 340,230 370,200 370,155 ; 555,1210 565,1220 587.8,1242.8 599.86,1242.8 ; 570,610 577.8,617.8 577.8,620.02 ; 1730,1545 1738.98,1553.98 1738.98,1561.46 ; 2265,1295 2272.72,1295 2292.73,1315.02
  lines w8: 2360,975 2370,985 2370,1010 2382.73,1022.73 2385.02,1022.73
  lines w10: 1078.83,1379.33 ccw(c1409.45,890) 1943.55,638.04 ; 1290,1240 1290,1310 ; 1595.14,1450.6 cw(c1409.45,890) 1942.55,1144.07 ; 1290,1310 1300,1300 1280,1300 1290,1310
  text "'.PRJ_Number'.PCB_Rev" at -40,1430 h80
  text "K" at 3125,1340 h30
  text "A" at 3120,1280 h30
  text "K" at 2825,1005 h30
  text "A" at 2825,945 h30
  text "A" at 2880,140 h30
  text "K" at 2880,80 h30
  text ".Layer_Name" at 523.85,-858.49 h60
Bottom Overlay:
  circle w8: c3019,667 r5.39
  lines w6: 2959,579 3030,579 3030,651 2959,651 2959,579
  text ".Layer_Name" at 523.85,-858.49 h60
Top Paste:
  text ".Layer_Name" at 523.85,-858.49 h60
Bottom Paste:
  text ".Layer_Name" at 523.85,-858.49 h60
Top Solder:
  text ".Layer_Name" at 523.85,-858.49 h60
  text ".Layer_Name" at 523.85,-858.49 h60
Bottom Solder:
  text ".Layer_Name" at 523.85,-858.49 h60
M1 Board Outline:
  the board outline again, w10
  text "M1 Board Outline" at 523.85,-858.49 h60
M2 Board Dimensions:
  rectangle: -53.15,-275 71.85,-150
  rectangle: 71.85,-400 446.85,-275
  lines w7: -53.15,-275 946.85,-275 ; 71.85,-400 71.85,-150 ; 196.85,-400 196.85,-150 ; 446.85,-400 446.85,-150 ; 696.85,-400 696.85,-150 ; -53.15,-400 946.85,-400 946.85,-150 -53.15,-150 -53.15,-400
M3 3D STEP Top:
  text ".Layer_Name" at 523.85,-858.49 h60
M4 3D STEP Bottom:
  text ".Layer_Name" at 523.85,-858.49 h60
M5 Assembly Top:
  circle w10: c1310,1475 r7.07
  circle w10: c3255,1495 r21.02
  circle w10: c155,510 r21.02
  circle w10: c1550,235 r21.02
  circle w10: c1180,235 r21.02
  circle w10: c535,1275 r8.99
  circle w10: c1717.76,1760.98 r8.99
  circle w10: c2660,1465 r7.81
  circle w10: c2660,1235 r7.81
  circle w10: c2261,227 r7.81
  circle w10: c880,185 r8.53
  circle w10: c540,780 r7.07
  circle w10: c2500,1250 r7.07
  circle w10: c2235,1250 r7.07
  lines w8: 447.34,1258.98 512.34,1258.98 512.34,1383.98 447.34,1383.98 447.34,1258.98 ; 1740.26,1652.01 1805.26,1652.01 1805.26,1777.01 1740.26,1777.01 1740.26,1652.01
  lines w10: -345.15,-930.17 6254.85,-930.17 ; -345.15,-726.83 6256.85,-726.83 ; -345.15,-523.5 -345.15,-1133.5 3659.85,-1133.5 6256.85,-1133.5 6256.85,-523.5 -344.65,-523.5 -344.65,-1133.5 1230.85,-1133.5 ; 2119.85,-1133.5 2119.85,-523.5 ; 3386.85,-726.83 3386.85,-523.5 ; 4226.85,-726.83 4226.85,-523.5 ; 4848.85,-1140 4848.85,-937.17
  text "COMPONENTS MARKED 'DNP' SHOULD NOT BE POPULATED." at 1100.35,-318.5 h60
  text "ASSEMBLY VARIANT:" at 1099.85,-434 h60
  text ".VariantName" at 2135.85,-434 h60
  text "PCB VIEWED FROM TOP SIDE" at -281.65,-655.67 h60
  text "BOARD #:" at 2194.85,-655.67 h60
  text ".PRJ_Number" at 2740.35,-655.67 h60
  text "REV:" at 3584.85,-655.67 h60
  text ".PCB_Rev" at 3876.35,-655.67 h60
  text "SVN REV:" at 4422.85,-655.67 h60
  text ".VersionControl_RevNumber" at 4928.85,-655.67 h60
  text "LAYER NAME =" at -282.65,-857.49 h60
  text "TID #:" at 2194.85,-859 h60
  text ".TID" at 2740.35,-859 h60
  text ".Layer_Name" at 511,-886 h60
  text "PLOT NAME =" at -281.65,-1064.34 h60
  text ".plot_File_Name" at 523.85,-1064.34 h60
  text "GENERATED    :" at 2196.85,-1064.34 h60
  text ".Print_Date" at 3066.35,-1064.34 h60
  text ".Print_Time" at 3795.35,-1064.34 h60
  text "TEXAS INSTRUMENTS" at 5059.85,-1064.34 h60
M6 Assembly Bottom:
  lines w10: -345.65,-727.33 6256.35,-727.33 ; -343.65,-930.67 6256.35,-930.67 ; 1062.35,-1140.5 1062.35,-937.67 ; 1684.35,-727.33 1684.35,-524 ; 2524.35,-727.33 2524.35,-524 ; 3791.35,-1134 3791.35,-524 ; 4680.35,-1134 6255.85,-1134 6255.85,-524 -345.65,-524 -345.65,-1134 2251.35,-1134 6256.35,-1134 6256.35,-524
  text "COMPONENTS MARKED 'DNP' SHOULD NOT BE POPULATED." at 6048.85,-318 h60
  text ".VariantName" at 5004.85,-434 h60
  text "ASSEMBLY VARIANT:" at 6043.85,-434 h60
  text ".VersionControl_RevNumber" at 982.35,-656.17 h60
  text "SVN REV:" at 1488.35,-656.17 h60
  text ".PCB_Rev" at 2034.85,-656.17 h60
  text "REV:" at 2326.35,-656.17 h60
  text ".PRJ_Number" at 3170.85,-656.17 h60
  text "BOARD #:" at 3716.35,-656.17 h60
  text "PCB VIEWED FROM BOTTOM SIDE" at 6192.85,-656.17 h60
  text ".TID" at 3170.85,-859.5 h60
  text "TID #:" at 3716.35,-859.5 h60
  text ".Layer_Name" at 5186.85,-863 h60
  text "LAYER NAME =" at 6005.85,-868 h60
  text "TEXAS INSTRUMENTS" at 851.35,-1064.84 h60
  text ".Print_Time" at 2115.85,-1064.84 h60
  text ".Print_Date" at 2844.85,-1064.84 h60
  text "GENERATED    :" at 3714.35,-1064.84 h60
  text ".plot_File_Name" at 5387.35,-1064.84 h60
  text "PLOT NAME =" at 6192.85,-1064.84 h60
M9 Title Sheet:
  drawing of 57 lines, arcs and shapes, not listed
  text "1" at 686.69,8036.5 h70
  text "2" at 3182.35,8036.5 h70
  text "3" at 5671.69,8036.5 h70
  text "4" at 8178.36,8036.5 h70
  text "5" at 10677.35,8036.5 h70
  text "6" at 13182.35,8036.5 h70
  text "A" at -469.65,6893.5 h70
  text "A" at 14330.35,6893.5 h70
  text "B" at -469.65,4513.5 h70
  text "B" at 14330.35,4513.5 h70
  text "C" at -469.65,2138.5 h70
  text "C" at 14330.35,2138.5 h70
  text "PROJECT TITLE:" at 11290.35,277.5 h45
  text ".PRJ_Title" at 11340.35,144.17 h70
  text "DESIGNED FOR:" at 11290.35,-23.5 h45
  text ".PRJ_Customer" at 11340.35,-163.5 h70
  text "D" at -469.65,-231.5 h70
  text "D" at 14330.35,-231.5 h70
  text "FILE NAME:" at 11290.35,-323.5 h45
  text ".PCB_File_Name_No_Path" at 11340.35,-443.5 h70
  text "Texas Instruments (TI) and/or its licensors do not warrant the accuracy or completeness of this specification" at 6320.85,-605.34 h45
  text "ENGINEER:" at 11290.35,-613.5 h45
  text "LAYOUT BY:" at 12795.35,-613.5 h45
  text "or any information contained therein. TI and/or its licensors do not warrant that this design will meet" at 6275.86,-718 h45
  text ".PRJ_Engineer" at 11340.35,-768.49 h70
  text ".PCB_Layout" at 12845.85,-768.49 h70
  text "the specifications, will be suitable for your application or fit for any particular purpose, or will operate in" at 6275.86,-830.67 h45
  text "ALTIUM DESIGNER VERSION:" at 12795.35,-923.5 h45
  text "an implementation. TI and/or its licensors do not warrant that the design is production worthy. You should" at 6275.86,-943.33 h45
  text "completely validate and test your design implementation to confirm the system functionality for your application." at 6320.85,-1056 h45
  text ".print_Scale" at 11340.35,-1056.83 h70
  text ".Application_BuildNumber" at 12845.85,-1056.83 h70
  text "1" at 686.69,-1263.5 h70
  text "2" at 3182.35,-1263.5 h70
  text "3" at 5671.69,-1263.5 h70
  text "4" at 8178.36,-1263.5 h70
  text "5" at 10677.35,-1263.5 h70
  text "6" at 13182.35,-1263.5 h70
M10 Fab Notes:
  drawing of 189 lines, arcs and shapes, not listed
  text "DESIGN INFORMATION" at 12324.87,6201 h60
  text "MIL" at 12971.85,6029 h60
  text "MIN. TRACK WIDTH:" at 11680.31,6021 h60
  text "6" at 12736.85,6020 h60
  text "6.862" at 12665,5893 h60
  text "MIN. CLEARANCE:" at 11680.31,5889 h60
  text "MIL" at 12974.85,5888 h60
  text "MIN. VIA PAD SIZE:" at 11680.31,5757 h60
  text "MIL" at 12975.85,5757 h60
  text "19.685" at 12608.85,5756 h60
  text "0.15mm (5.9055MIL)" at 12375.31,5615.29 h60
  text "EXTERNAL" at 13246,5612 h60
  text "MINIMUM ANNULAR RING" at 11351.08,5611 h60
  text "PER" at 11551.08,5493 h60
  text "IPC-D-275 CLASS 2 LEVEL C" at 11771.08,5493 h60
  text "MIL, HOLES" at 13259.31,5380.71 h60
  text "+/-" at 12866.85,5380 h60
  text "+/-" at 13720.85,5380 h60
  text "REGISTRATION TOLERANCES:" at 11351.08,5375 h60
  text "METAL" at 12550.85,5375 h60
  text "5" at 13127.05,5375 h60
  text "3" at 13960.05,5375 h60
  text "MIL" at 14076.31,5375 h60
  text "+/-" at 13720.85,5262 h60
  text "HOLE SIZE TOLERANCE (UNLESS OTHERWISE SPECIFIED):" at 11351.08,5257 h60
  text "3" at 13960.05,5257 h60
  text "MIL" at 14076.31,5257 h60
  text "MATERIAL:" at 11276.31,5047.54 h60
  text "FR-4 High Tg" at 12262.75,4907.21 h60
  text "FR-408" at 11697.31,4898.64 h60
  text "OTHER" at 13185.31,4898.64 h60
  text "X" at 12107.85,4895 h60
  text "63 MIL (1.6mm) +/-10%" at 12017.41,4735.92 h60
  text "THICKNESS:" at 11351.08,4731.64 h60
  text "X" at 11889.25,4731.64 h60
  text "OTHER" at 13302.31,4731.64 h60
  text "TOLERANCE:" at 11351.08,4573.64 h60
  text "X" at 12190.38,4573.64 h60
  text "ANSI IPC-6012 TYPE 3 CLASS 2" at 12377.33,4573.64 h60
  text "OTHER +/-" at 12377.31,4417.64 h60
  text "BOW & TWIST:" at 11351.08,4260.64 h60
  text "X" at 12190.38,4260.64 h60
  text "ANSI IPC-6012 TYPE 3 CLASS 2" at 12377.33,4260.64 h60
  text "OTHER +/-" at 12377.31,4102.13 h60
  text "DRILLING:" at 11276.31,3963.64 h60
  text "REFERENCE:" at 11351.08,3846.64 h60
  text "X" at 11999.31,3846.64 h60
  text "AS SHOWN" at 12186.31,3846.64 h60
  text "X" at 12900.31,3846.64 h60
  text "NC_DRILL FILES" at 13037.31,3846.64 h60
  text "PTH COPPER THICKNESS:" at 11351.08,3688.64 h60
  text "X" at 12481.31,3688.64 h60
  text "20-30 um" at 12618.31,3688.64 h60
  text "OTHER" at 13335.31,3688.64 h60
  text "BOARD FINISH:" at 11276.31,3529.64 h60
  text "SILKSCREEN:" at 11431.53,3411.64 h60
  text "X" at 12380.31,3411.64 h60
  text "TOP" at 12506.31,3411.64 h60
  text "X" at 12890.31,3411.64 h60
  text "BOTTOM" at 13017.31,3411.64 h60
  text "SILKSCREEN COLOR:" at 11431.53,3244.64 h60
  text "X" at 12379.27,3244.64 h60
  text "WHITE" at 12506.31,3244.64 h60
  text "OTHER" at 13017.31,3244.64 h60
  text "X" at 12510.27,3085.44 h60
  text "GREEN" at 12637.31,3085.44 h60
  text "OTHER" at 13255.31,3085.44 h60
  text "SOLDER RESIST COLOR:" at 11431.53,3074.64 h60
  text "X" at 12510.27,2915.44 h60
  text "MATTE" at 12637.31,2915.44 h60
  text "SEMI-GLOSS" at 13254.85,2914.8 h60
  text "IMMERSION GOLD (ENIG)" at 12337.31,2726.92 h60
  text "ENEPIG" at 13674.85,2723.64 h60
  text "SURFACE FINISH:" at 11276.31,2722.64 h60
  text "X" at 12150.36,2722.64 h60
  text "IMM. TIN/SILVER OR EQUIV" at 11605.85,2565.64 h60
  text "OTHER" at 13037.31,2565.64 h60
  text "ARRAY/PANEL:" at 11276.31,2386.64 h60
  text "CUT AND TRIM PER M1 BOARD OUTLINE" at 12337.31,2382.35 h60
  text "N.C. ROUTE" at 12337.31,2230.64 h60
  text "X" at 13016.31,2230.64 h60
  text "V. SCORE" at 13203.31,2230.64 h60
  text "CERTIFICATION:" at 11276.31,2093.64 h60
  text "MATERIALS AND WORKMANSHIP FOR ALL PCBS" at 12001.31,2093.64 h60
  text "TO MEET OR EXCEED THE REQUIREMENTS OF:" at 12001.31,1995.64 h60
  text "X" at 11627.81,1859.13 h60
  text "ANSI IPC-A-600F CLASS ->" at 11766.81,1859.13 h60
  text "X" at 13405.87,1859.13 h60
  text "2" at 13524.81,1859.14 h60
  text "1" at 13209.81,1857.64 h60
  text "3" at 13878.81,1857.64 h60
  text "X" at 12441.87,1699.64 h60
  text "RoHS" at 12578.81,1699.64 h60
  text "OTHER" at 13223.21,1699.64 h60
  text "PER ORDER" at 13620.27,1699.64 h60
  text "ALL BOARDS MUST MEET OR EXCEED UL94-V0 REQUIREMENTS." at 11303.85,1534 h60
  text "PCB MUST BEAR THE UL94V-0 UL REGISTERED MATERIAL ID NUMBER" at 11303.85,1414 h60
  text "VIA TENTING:" at 12452.85,1263 h60
  text "X" at 13212.85,1261 h60
  text "YES" at 13002.52,1253.92 h60
  text "NO" at 13367.32,1248.69 h60
  text "ADDITIONAL REQUIREMENTS:" at 11276.31,1240.64 h60
  text "IMPEDANCE CONTROL:" at 12474.85,1134 h60
  text "YES" at 13458.85,1133 h60
  text "MICROSECTION:" at 11351.08,1125.64 h60
  text "YES" at 12256.81,1125.64 h60
  text "X" at 14000.85,1126 h60
  text "NO" at 13834.32,1115.69 h60
  text "REQUIRED" at 13118.31,969.49 h60
  text "BARE BOARD ELEC. TEST:" at 11351.08,966.64 h60
  text "NONE" at 12656.81,966.64 h60
  text "X" at 12991.31,966.64 h60
  text "PER ORDER" at 13710.31,966.64 h60
M11 Gerber Information:
  lines w10: -345.15,-930.17 6254.85,-930.17 ; -345.15,-726.83 6256.85,-726.83 ; -345.15,-523.5 -345.15,-1133.5 3659.85,-1133.5 6256.85,-1133.5 6256.85,-523.5 -344.65,-523.5 -344.65,-1133.5 1230.85,-1133.5 ; 2119.85,-1133.5 2119.85,-523.5 ; 3386.85,-726.83 3386.85,-523.5 ; 4226.85,-726.83 4226.85,-523.5 ; 4848.85,-1140 4848.85,-937.17
  text "ALL ARTWORK VIEWED FROM TOP SIDE" at -281.65,-655.67 h60
  text "BOARD #:" at 2194.85,-655.67 h60
  text ".PRJ_Number" at 2740.35,-655.67 h60
  text "REV:" at 3584.85,-655.67 h60
  text ".PCB_Rev" at 3876.35,-655.67 h60
  text "SVN REV:" at 4422.85,-655.67 h60
  text ".VersionControl_RevNumber" at 4928.85,-655.67 h60
  text "LAYER NAME =" at -281.65,-858.49 h60
  text "TID #:" at 2194.85,-859 h60
  text ".TID" at 2740.35,-859 h60
  text "PLOT NAME =" at -281.65,-1064.34 h60
  text ".plot_File_Name" at 523.85,-1064.34 h60
  text "GENERATED    :" at 2196.85,-1064.34 h60
  text ".Print_Date" at 3066.35,-1064.34 h60
  text ".Print_Time" at 3795.35,-1064.34 h60
  text "TEXAS INSTRUMENTS" at 5059.85,-1064.34 h60
M12 Stackup:
  drawing of 191 lines, arcs and shapes, not listed
  text "Layer" at 9737.19,7830 h60
  text "Name" at 10147.11,7830 h60
  text "Material" at 11076.85,7830 h60
  text "Thickness" at 11936.62,7830 h60
  text "Constant" at 12586.45,7830 h60
  text "Board Layer Stack" at 13156.31,7830 h60
  text "1" at 9737.19,7710 h60
  text "Top Overlay" at 10147.11,7710 h60
  text "2" at 9737.19,7590 h60
  text "Top Solder" at 10147.11,7590 h60
  text "Solder Resist" at 11076.85,7590 h60
  text "0.40mil" at 11936.62,7590 h60
  text "3.5" at 12586.45,7590 h60
  text "3" at 9737.19,7470 h60
  text "Top Layer" at 10147.11,7470 h60
  text "Copper" at 11076.85,7470 h60
  text "1.40mil" at 11936.62,7470 h60
  text "4" at 9737.19,7350 h60
  text "Dielectric1" at 10147.11,7350 h60
  text "FR-4 High Tg" at 11076.85,7350 h60
  text "59.20mil" at 11936.62,7350 h60
  text "4.8" at 12586.45,7350 h60
  text "5" at 9737.19,7230 h60
  text "Bottom Layer" at 10147.11,7230 h60
  text "Copper" at 11076.85,7230 h60
  text "1.40mil" at 11936.62,7230 h60
  text "6" at 9737.19,7110 h60
  text "Bottom Solder" at 10147.11,7110 h60
  text "Solder Resist" at 11076.85,7110 h60
  text "0.40mil" at 11936.62,7110 h60
  text "3.5" at 12586.45,7110 h60
  text "7" at 9737.19,6990 h60
  text "Bottom Overlay" at 10147.11,6990 h60
M13 Component Bodies Top:
  text ".Layer_Name" at 523.85,-858.49 h60
M14 Component Bodies Bottom:
  text ".Layer_Name" at 523.85,-858.49 h60
M15 Courtyards Top:
  text ".Layer_Name" at 523.85,-858.49 h60
M16 Courtyards Bottom:
  text ".Layer_Name" at 523.85,-858.49 h60
Drill Drawing:
  circle w10: c4468.82,1467.37 r16.6
  circle w10: c4468.82,1467.37 r27.67
  circle w10: c4468.82,969.37 r27.67
  lines w10: 4441.16,706.53 4454.99,706.53 4454.99,692.7 4482.66,692.7 4482.66,706.53 4496.49,706.53 4496.49,734.2 4482.66,734.2 4482.66,748.03 4454.99,748.03 4454.99,734.2 4441.16,734.2 4441.16,706.53 ; 4441.16,817.2 4441.16,831.03 4454.99,844.87 4441.16,858.7 4441.16,872.53 4454.99,872.53 4468.82,858.7 4482.66,872.53 4496.49,872.53 4496.49,858.7 4482.66,844.87 4496.49,831.03 4496.49,817.2 4482.66,817.2 4468.82,831.03 4454.99,817.2 4441.16,817.2 ; 4441.16,1121.53 4496.49,1121.53 4468.82,1066.2 4441.16,1121.53 ; 4441.16,1190.7 4496.49,1190.7 4496.49,1246.03 4441.16,1246.03 4441.16,1190.7 ; 4441.16,1315.2 4468.82,1329.03 4496.49,1315.2 4482.66,1342.87 4496.49,1370.53 4468.82,1356.7 4441.16,1370.53 4454.99,1342.87 4441.16,1315.2 ; 4441.16,1591.87 4468.82,1564.2 4496.49,1591.87 4468.82,1619.53 4441.16,1591.87 ; 4441.16,1688.7 4496.49,1688.7 4496.49,1744.03 4441.16,1744.03 4441.16,1688.7 ; 4452.23,1699.77 4485.43,1699.77 4485.43,1732.97 4452.23,1732.97 4452.23,1699.77
  lines w12: 4391,655.35 7656.09,655.35 ; 4391,1775.85 7656.09,1775.85 ; 4729.01,530.85 4729.01,1900.35 ; 5061.17,530.85 5061.17,1900.35 ; 5697.65,530.85 5697.65,1900.35 ; 5956.85,530.85 5956.85,1900.35 ; 6332.09,530.85 6332.09,1900.35 ; 7056.64,530.85 7056.64,1900.35 ; 4391,530.85 7656.09,530.85 7656.09,1900.35 4391,1900.35 4391,530.85
  text "DRILL TABLE" at 4390,2027 h80
  text "Symbol" at 4465.7,1813.2 h72
  text "Quantity" at 4766.36,1813.2 h72
  text "Finished Hole Size" at 5098.52,1813.2 h72
  text "Plated" at 5735,1813.2 h72
  text "Hole Type" at 5994.2,1813.2 h72
  text "Drill Layer Pair" at 6369.44,1813.2 h72
  text "Hole Length" at 7093.99,1813.2 h72
  text "7" at 4766.36,1688.7 h60
  text "7.87mil (0.200mm)" at 5098.52,1688.7 h60
  text "PTH" at 5735,1688.7 h60
  text "Round" at 5994.2,1688.7 h60
  text "Top Layer - Bottom Layer" at 6369.44,1688.7 h60
  text "-" at 7093.99,1688.7 h60
  text "177" at 4766.36,1564.2 h60
  text "12.00mil (0.305mm)" at 5098.52,1564.2 h60
  text "PTH" at 5735,1564.2 h60
  text "Round" at 5994.2,1564.2 h60
  text "Top Layer - Bottom Layer" at 6369.44,1564.2 h60
  text "-" at 7093.99,1564.2 h60
  text "8" at 4766.36,1439.7 h60
  text "16.00mil (0.406mm)" at 5098.52,1439.7 h60
  text "PTH" at 5735,1439.7 h60
  text "Round" at 5994.2,1439.7 h60
  text "Top Layer - Bottom Layer" at 6369.44,1439.7 h60
  text "-" at 7093.99,1439.7 h60
  text "2" at 4766.36,1315.2 h60
  text "17.72mil (0.450mm)" at 5098.52,1315.2 h60
  text "PTH" at 5735,1315.2 h60
  text "Round" at 5994.2,1315.2 h60
  text "Top Layer - Bottom Layer" at 6369.44,1315.2 h60
  text "-" at 7093.99,1315.2 h60
  text "8" at 4766.36,1190.7 h60
  text "27.56mil (0.700mm)" at 5098.52,1190.7 h60
  text "PTH" at 5735,1190.7 h60
  text "Round" at 5994.2,1190.7 h60
  text "Top Layer - Bottom Layer" at 6369.44,1190.7 h60
  text "-" at 7093.99,1190.7 h60
  text "12" at 4766.36,1066.2 h60
  text "35.43mil (0.900mm)" at 5098.52,1066.2 h60
  text "PTH" at 5735,1066.2 h60
  text "Round" at 5994.2,1066.2 h60
  text "Top Layer - Bottom Layer" at 6369.44,1066.2 h60
  text "-" at 7093.99,1066.2 h60
  text "15" at 4766.36,941.7 h60
  text "40.00mil (1.016mm)" at 5098.52,941.7 h60
  text "PTH" at 5735,941.7 h60
  text "Round" at 5994.2,941.7 h60
  text "Top Layer - Bottom Layer" at 6369.44,941.7 h60
  text "-" at 7093.99,941.7 h60
  text "2" at 4766.36,817.2 h60
  text "43.31mil (1.100mm)" at 5098.52,817.2 h60
  text "PTH" at 5735,817.2 h60
  text "Round" at 5994.2,817.2 h60
  text "Top Layer - Bottom Layer" at 6369.44,817.2 h60
  text "-" at 7093.99,817.2 h60
  text "2" at 4766.36,692.7 h60
  text "65.00mil (1.651mm)" at 5098.52,692.7 h60
  text "NPTH" at 5735,692.7 h60
  text "Rectangle" at 5994.2,692.7 h60
  text "Top Layer - Bottom Layer" at 6369.44,692.7 h60
  text "82.00mil (2.083mm)" at 7093.99,692.7 h60
  text "233 Total" at 4766.36,568.2 h60
  text "Slot definitions :" at 4465.7,481.05 h60
  text "Routed Path Length" at 4916.35,481.05 h60
  text "= Calculated from tool start centre position to tool end centre position." at 5456.2,481.05 h60
  text "Hole Length" at 4916.35,431.25 h60
  text "= Routed Path Length + Tool Size = Slot length as defined in the PCB layout" at 5256.35,431.25 h60
  text "FOR 7.87MIL DRILL +0/-7.87MIL" at 4393,284 h80
  text "FOR 12MIL DRILL +0/-12MIL" at 4395,194 h80
  text "FOR 16MIL DRILL +0/-16MIL" at 4398,98 h80
  text "FOR PTH DRILL +/-3MIL" at 4398,1 h80
  text "FOR NPTH DRILL +/-2MIL" at 4399,-82 h80
  text ".Layer_Name" at 523.85,-858.49 h60
M17 Embedded Cavity:
  text ".Layer_Name" at 523.85,-858.49 h60
M18 Embedded Assembly:
  text ".Layer_Name" at 523.85,-858.49 h60
M19 Embedded Keepout:
  text ".Layer_Name" at 523.85,-858.49 h60

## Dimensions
-53.15,-400 to 946.85,-400 on M2 Board Dimensions
0,0 to 0,1968.5 on M2 Board Dimensions
0,0 to 3346.46,0 on M2 Board Dimensions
